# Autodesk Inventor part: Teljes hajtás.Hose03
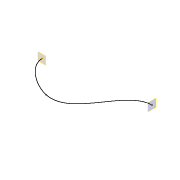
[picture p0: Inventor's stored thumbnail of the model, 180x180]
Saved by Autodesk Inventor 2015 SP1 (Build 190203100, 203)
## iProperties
ActiveState: True
Angle: UnInitValue
BendRadius: 0.500 in
CouplingKey: UnInitValue
DefaultBendRadius: UnInitValue
Diameter: 1/4
DiameterType: Nominal
Elbow45Key: UnInitValue
Elbow90Key: UnInitValue
ElbowCustomKey: UnInitValue
Ending: UnInitValue
FittingMaterial: UnInitValue
FittingStandard: UnInitValue
FlangeKey: UnInitValue
Gap: UnInitValue
GasketKey: UnInitValue
ID: 0,635
IsButtWelded: UnInitValue
IsFlanged: UnInitValue
IsSelfDraining: UnInitValue
Material: UnInitValue
MixedUnits: UnInitValue
Name: Hydraulic Hose - No Fittings
OD: 1,4986
PipeKey: v3#d489867e-ac9b-47ea-b952-0a1b885f66be#1
PipeType: Flexible Hose
PipingComponentColor: Blue - Wall Paint - Glossy
RoundUpValue: 0.125 in
RouteDirection45: UnInitValue
RouteDirection90: UnInitValue
Schedule: ID=0.25
ShowGap: UnInitValue
Standard: UnInitValue
SuppressEndFitting: True
SuppressStartFitting: True
UseFlangsForCouplings: UnInitValue
UseSubASM: True
_ComponentInfo: <CS><C N="Pipe" R="0,749300" OR="0,749300" IR="0,317500" PL="PL" PartType="pipe" SymKey="" PN="Parker hidraulikatömlő - No Skive 1/4"><CO N="1"><FE V="0"/><FD V
StyleName: _Piping Style 20
Created: 2013-02
Part Number: Teljes hajtás.Hose03
Material: Generic
Document SubType Name: Modeling
Designer: Marci
Density: 1 g/cm^3
Appearance: Default
_PSKETCH_SNAP: False
_PSKETCH_RSNP: False
_BASENETWORK_NOTAUTODIMENSION: False
Author: Marci
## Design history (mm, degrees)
workpoint "Work Point1"
workplane "Work Plane1"
workpoint "Work Point2"
workplane "Work Plane2"
sketch "3D Sketch1" dims "d0" = 10, "d1" = 0.1 (derived), "d2" = 10, "d3" = 0.1 (derived)
other parameters: "B" = 12.7 [user parameter]
